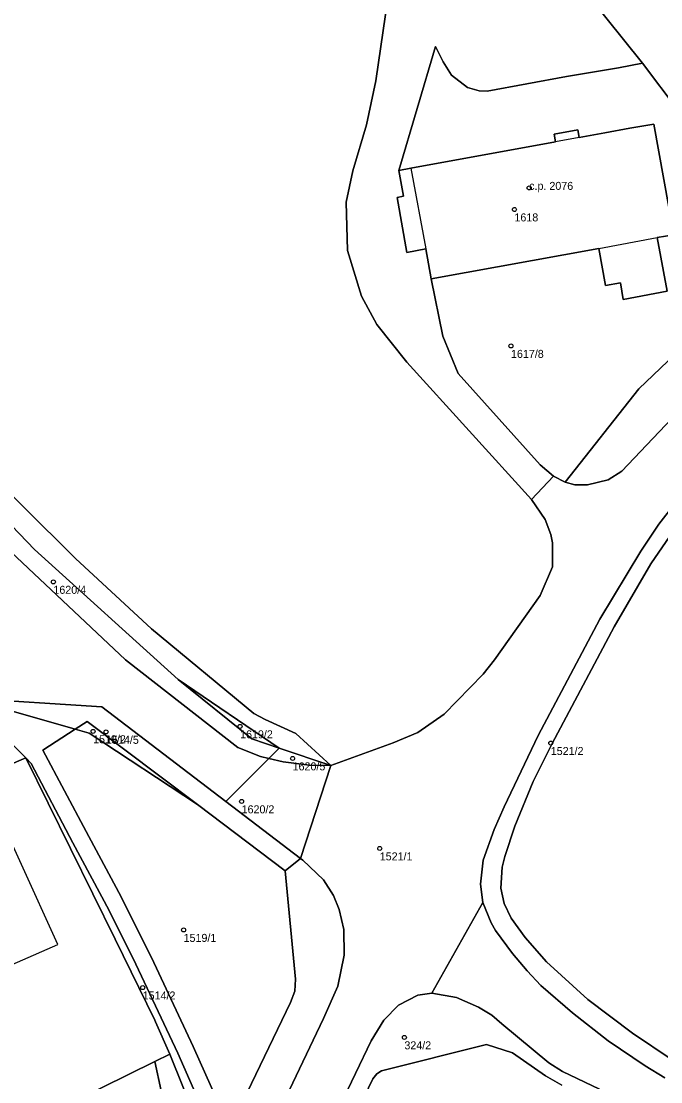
# Model space of a CAD drawing. Extents: x -878211 to -870363, y -1058464 to -1052522.
# Drawn here: x -874750.5 to -874670.5, y -1056026.5 to -1055893.9 of the extents above; entities that cross this region are included whole.
import ezdxf

# ---------------------------------------------------------------- set-up
doc = ezdxf.new("R2010")
doc.units = 0
for name, color, linetype in [('Definiční body', 7, 'Continuous'), ('Polygon budovy', 7, 'Continuous'), ('Polygon parcely', 7, 'Continuous')]:
    doc.layers.add(name, color=color, linetype=linetype)

msp = doc.modelspace()

# ---------------------------------------------------------------- linework, layer by layer
at = {"layer": 'Definiční body'}
for centre in [(-874686.99, -1055914.72994), (-874688.83, -1055917.42994), (-874689.26, -1055934.48994), (-874746.44, -1055963.97994), (-874741.48, -1055982.65994), (-874739.86, -1055982.72994), (-874723.11, -1055982.03994), (-874684.29, -1055984.12994), (-874716.55, -1055986.04994), (-874722.92, -1055991.41994), (-874705.66, -1055997.29994), (-874730.17, -1056007.48994), (-874735.28, -1056014.68994), (-874702.58, -1056020.91994)]:
    msp.add_circle(centre, 0.25, dxfattribs=at)
at = {"layer": 'Polygon budovy'}
for points in [[(-874701.77, -1055912.28), (-874699.91, -1055922.36), (-874699.24, -1055926.08), (-874678.28, -1055922.29), (-874671.01, -1055920.95), (-874668.92, -1055920.58), (-874671.43, -1055906.75), (-874674.4, -1055907.27), (-874677.53, -1055907.83), (-874680.73, -1055908.42), (-874683.69, -1055908.98)], [(-874764.98, -1055993.72), (-874755.99, -1056013.73), (-874745.88, -1056009.32), (-874755, -1055989.3)]]:
    msp.add_lwpolyline(points, close=True, dxfattribs=at)
at = {"layer": 'Polygon parcely'}
for points in [[(-874756.95, -1055947.89), (-874743.69, -1055961.07), (-874734.19, -1055969.86), (-874721.38, -1055980.44), (-874719.97, -1055981.18), (-874716.14, -1055982.94), (-874711.78, -1055986.92), (-874703.97, -1055984.1), (-874700.92, -1055982.82), (-874697.6, -1055980.52), (-874692.73, -1055975.53), (-874691.31, -1055973.73), (-874685.62, -1055965.69), (-874684.06, -1055962.1), (-874684.06, -1055959.08), (-874684.28, -1055958.07), (-874684.99, -1055956.18), (-874686.68, -1055953.68), (-874702.29, -1055936.53), (-874706.04, -1055931.81), (-874707.93, -1055928.26), (-874709.71, -1055922.56), (-874709.86, -1055916.51), (-874709.03, -1055912.59), (-874707.3, -1055906.85), (-874706.13, -1055901.34), (-874704.05, -1055887.02)], [(-874704.05, -1055887.02), (-874706.13, -1055901.34), (-874707.3, -1055906.85), (-874709.03, -1055912.59), (-874709.86, -1055916.51), (-874709.71, -1055922.56), (-874707.93, -1055928.26), (-874706.04, -1055931.81), (-874702.29, -1055936.53), (-874686.68, -1055953.68), (-874683.95, -1055950.78), (-874685.63, -1055949.35), (-874695.87, -1055937.91), (-874697.78, -1055933.25), (-874699.24, -1055926.08), (-874699.91, -1055922.36), (-874702.26, -1055922.81), (-874703.5, -1055915.91), (-874702.69, -1055915.75), (-874703.28, -1055912.55), (-874698.71, -1055897.06), (-874697.73, -1055898.97), (-874696.71, -1055900.66), (-874694.7, -1055902.18), (-874693.25, -1055902.59), (-874692.22, -1055902.64), (-874682.33, -1055900.81), (-874675.84, -1055899.73), (-874672.82, -1055899.15), (-874679.61, -1055890.66)], [(-874679.61, -1055890.66), (-874672.82, -1055899.15), (-874668.36, -1055905.05), (-874663.17, -1055930.38), (-874659.49, -1055927.14), (-874653.58, -1055922.94), (-874645.33, -1055917.81), (-874639.84, -1055915.02), (-874631.91, -1055911.94), (-874623.73, -1055909.15), (-874623.3, -1055907.36), (-874623.18, -1055905.33), (-874623.7, -1055903.03), (-874633.81, -1055890.41)], [(-874668.36, -1055905.05), (-874672.82, -1055899.15), (-874675.84, -1055899.73), (-874682.33, -1055900.81), (-874692.22, -1055902.64), (-874693.25, -1055902.59), (-874694.7, -1055902.18), (-874696.71, -1055900.66), (-874697.73, -1055898.97), (-874698.71, -1055897.06), (-874703.28, -1055912.55), (-874701.77, -1055912.28), (-874683.69, -1055908.98), (-874683.88, -1055908), (-874680.9, -1055907.46), (-874680.73, -1055908.42), (-874677.53, -1055907.83), (-874674.4, -1055907.27), (-874671.43, -1055906.75), (-874668.92, -1055920.58), (-874671.01, -1055920.95), (-874669.74, -1055927.65), (-874675.24, -1055928.66), (-874675.56, -1055926.59), (-874677.45, -1055926.91), (-874678.28, -1055922.29), (-874699.24, -1055926.08), (-874697.78, -1055933.25), (-874695.87, -1055937.91), (-874685.63, -1055949.35), (-874683.95, -1055950.78), (-874682.5, -1055951.51), (-874673.28, -1055939.83), (-874666.08, -1055932.96)], [(-874666.08, -1055932.96), (-874673.28, -1055939.83), (-874682.5, -1055951.51), (-874681.3, -1055951.84), (-874679.71, -1055951.83), (-874677.1, -1055951.24), (-874675.43, -1055950.15), (-874662.18, -1055936.17)], [(-874662.18, -1055936.17), (-874675.43, -1055950.15), (-874677.1, -1055951.24), (-874679.71, -1055951.83), (-874681.3, -1055951.84), (-874682.5, -1055951.51), (-874683.95, -1055950.78), (-874686.68, -1055953.68), (-874684.99, -1055956.18), (-874684.28, -1055958.07), (-874684.06, -1055959.08), (-874684.06, -1055962.1), (-874685.62, -1055965.69), (-874691.31, -1055973.73), (-874692.73, -1055975.53), (-874697.6, -1055980.52), (-874700.92, -1055982.82), (-874703.97, -1055984.1), (-874711.78, -1055986.92), (-874715.56, -1055998.56), (-874715.27, -1055998.76), (-874712.68, -1056001.22), (-874711.42, -1056003.18), (-874710.71, -1056004.93), (-874710.15, -1056007.45), (-874710.12, -1056010.62), (-874710.89, -1056014.52), (-874712.68, -1056018.57), (-874723.79, -1056041.89)], [(-874760.24, -1055948), (-874748.81, -1055959.95), (-874730.86, -1055976.16), (-874718.22, -1055984.76), (-874711.78, -1055986.92), (-874716.14, -1055982.94), (-874719.97, -1055981.18), (-874721.38, -1055980.44), (-874734.19, -1055969.86), (-874743.69, -1055961.07), (-874756.95, -1055947.89)], [(-874718.48, -1056045.86), (-874706.75, -1056021.33), (-874705.13, -1056018.77), (-874703.32, -1056016.88), (-874700.92, -1056015.63), (-874699.15, -1056015.39), (-874692.76, -1056004.06), (-874693.08, -1056001.75), (-874692.72, -1055998.76), (-874691.38, -1055994.94), (-874690.11, -1055992.09), (-874685.85, -1055983.17), (-874678.15, -1055968.65), (-874673.05, -1055960.14), (-874670.77, -1055956.77), (-874668.86, -1055954.3)], [(-874668.86, -1055954.3), (-874670.77, -1055956.77), (-874673.05, -1055960.14), (-874678.15, -1055968.65), (-874685.85, -1055983.17), (-874690.11, -1055992.09), (-874691.38, -1055994.94), (-874692.72, -1055998.76), (-874693.08, -1056001.75), (-874692.76, -1056004.06), (-874691.75, -1056006.58), (-874691.19, -1056007.55), (-874689.08, -1056010.44), (-874687.25, -1056012.6), (-874685.53, -1056014.41), (-874681.58, -1056017.86), (-874677.13, -1056021.34), (-874672.5, -1056024.45), (-874670.04, -1056025.99)], [(-874757.31, -1055978.52), (-874740.38, -1055979.61), (-874724.88, -1055991.44), (-874719.51, -1055986.05), (-874720.55, -1055985.8), (-874723.38, -1055984.67), (-874737.42, -1055973.71), (-874753.92, -1055958.22)], [(-874668.96, -1055957.59), (-874671.77, -1055961.73), (-874676.38, -1055969.58), (-874684.1, -1055984.19), (-874686.47, -1055988.93), (-874688.76, -1055994.5), (-874690.04, -1055998.29), (-874690.37, -1055999.65), (-874690.54, -1056002.26), (-874690.1, -1056004.19), (-874689.22, -1056006), (-874687.47, -1056008.44), (-874684.83, -1056011.49), (-874679.64, -1056016.16), (-874674.07, -1056020.38), (-874669.11, -1056023.72)], [(-874669.11, -1056023.72), (-874674.07, -1056020.38), (-874679.64, -1056016.16), (-874684.83, -1056011.49), (-874687.47, -1056008.44), (-874689.22, -1056006), (-874690.1, -1056004.19), (-874690.54, -1056002.26), (-874690.37, -1055999.65), (-874690.04, -1055998.29), (-874688.76, -1055994.5), (-874686.47, -1055988.93), (-874684.1, -1055984.19), (-874676.38, -1055969.58), (-874671.77, -1055961.73), (-874668.96, -1055957.59)], [(-874723.79, -1056041.89), (-874712.68, -1056018.57), (-874710.89, -1056014.52), (-874710.12, -1056010.62), (-874710.15, -1056007.45), (-874710.71, -1056004.93), (-874711.42, -1056003.18), (-874712.68, -1056001.22), (-874715.27, -1055998.76), (-874715.56, -1055998.56), (-874717.46, -1056000.09), (-874716.19, -1056013.63), (-874716.29, -1056015.13), (-874716.81, -1056016.56), (-874724.38, -1056032.3), (-874728.99, -1056022.04), (-874734.19, -1056010.92), (-874738.25, -1056002.8), (-874742.35, -1055995.2), (-874747.78, -1055985.01), (-874743.71, -1055982.38), (-874757.31, -1055978.52), (-874749.9, -1055985.99), (-874749.22, -1055986.7), (-874744.03, -1055996.59), (-874739.47, -1056005.07), (-874736.12, -1056011.78), (-874730.91, -1056022.87), (-874724.71, -1056036.91)], [(-874670.04, -1056025.99), (-874672.5, -1056024.45), (-874677.13, -1056021.34), (-874681.58, -1056017.86), (-874685.53, -1056014.41), (-874687.25, -1056012.6), (-874689.08, -1056010.44), (-874691.19, -1056007.55), (-874691.75, -1056006.58), (-874692.76, -1056004.06), (-874699.15, -1056015.39), (-874696.05, -1056015.93), (-874693.31, -1056017.12), (-874691.64, -1056018.14), (-874690.41, -1056019.24), (-874684.55, -1056024.09), (-874682.82, -1056025.19), (-874678.22, -1056027.38), (-874668.85, -1056031.63)], [(-874678.22, -1056027.38), (-874682.82, -1056025.19), (-874684.55, -1056024.09), (-874690.41, -1056019.24), (-874691.64, -1056018.14), (-874693.31, -1056017.12), (-874696.05, -1056015.93), (-874699.15, -1056015.39), (-874700.92, -1056015.63), (-874703.32, -1056016.88), (-874705.13, -1056018.77), (-874706.75, -1056021.33), (-874718.48, -1056045.86)], [(-874718.01, -1056050), (-874706.53, -1056026.09), (-874706.04, -1056025.49), (-874705.45, -1056025.1), (-874692.33, -1056021.8), (-874689.09, -1056022.83), (-874684.96, -1056025.73), (-874682.89, -1056026.9)], [(-874682.89, -1056026.9), (-874684.96, -1056025.73), (-874689.09, -1056022.83), (-874692.33, -1056021.8), (-874705.45, -1056025.1), (-874706.04, -1056025.49), (-874706.53, -1056026.09), (-874718.01, -1056050)]]:
    msp.add_lwpolyline(points, dxfattribs=at)
for points in [[(-874703.28, -1055912.55), (-874702.69, -1055915.75), (-874703.5, -1055915.91), (-874702.26, -1055922.81), (-874699.91, -1055922.36), (-874699.24, -1055926.08), (-874678.28, -1055922.29), (-874677.45, -1055926.91), (-874675.56, -1055926.59), (-874675.24, -1055928.66), (-874669.74, -1055927.65), (-874671.01, -1055920.95), (-874668.92, -1055920.58), (-874671.43, -1055906.75), (-874674.4, -1055907.27), (-874677.53, -1055907.83), (-874680.73, -1055908.42), (-874680.9, -1055907.46), (-874683.88, -1055908), (-874683.69, -1055908.98), (-874701.77, -1055912.28)], [(-874768.56, -1055938.23), (-874753.92, -1055958.22), (-874737.42, -1055973.71), (-874723.38, -1055984.67), (-874720.55, -1055985.8), (-874719.51, -1055986.05), (-874718.22, -1055984.76), (-874721.64, -1055983.61), (-874730.86, -1055976.16), (-874748.81, -1055959.95), (-874760.24, -1055948)], [(-874787.87, -1055982.66), (-874772.22, -1055996.04), (-874765.48, -1055992.98), (-874755.06, -1055988.17), (-874749.9, -1055985.99), (-874757.31, -1055978.52), (-874764.37, -1055984.28), (-874766.82, -1055986.47), (-874770.87, -1055989.91), (-874774.61, -1055986.86), (-874784.46, -1055977.65), (-874786.38, -1055974.79), (-874788.76, -1055977.69), (-874790.59, -1055979.93)], [(-874721.64, -1055983.61), (-874718.22, -1055984.76), (-874730.86, -1055976.16)], [(-874742.21, -1055981.41), (-874728.42, -1055991.82), (-874717.46, -1056000.09), (-874715.56, -1055998.56), (-874724.88, -1055991.44), (-874740.38, -1055979.61), (-874757.31, -1055978.52), (-874743.71, -1055982.38)], [(-874741.98, -1055982.87), (-874743.71, -1055982.38), (-874747.78, -1055985.01), (-874742.35, -1055995.2), (-874738.25, -1056002.8), (-874734.19, -1056010.92), (-874728.99, -1056022.04), (-874724.38, -1056032.3), (-874716.81, -1056016.56), (-874716.29, -1056015.13), (-874716.19, -1056013.63), (-874717.46, -1056000.09), (-874728.42, -1055991.82)], [(-874728.42, -1055991.82), (-874742.21, -1055981.41), (-874743.71, -1055982.38), (-874741.98, -1055982.87)], [(-874711.78, -1055986.92), (-874718.22, -1055984.76), (-874719.51, -1055986.05), (-874717.74, -1055986.47), (-874714.44, -1055986.89)], [(-874750.31, -1056032.09), (-874733.76, -1056023.92), (-874731.9, -1056023), (-874733.67, -1056018.96), (-874733.75, -1056018.77), (-874738.71, -1056008.63), (-874749.9, -1055985.99), (-874755.06, -1055988.17), (-874765.48, -1055992.98), (-874764.98, -1055993.72), (-874755.99, -1056013.73), (-874755.89, -1056017.1)], [(-874725.31, -1056039.38), (-874724.68, -1056037.94), (-874724.62, -1056037.43), (-874724.71, -1056036.91), (-874730.91, -1056022.87), (-874736.12, -1056011.78), (-874739.47, -1056005.07), (-874744.03, -1055996.59), (-874749.22, -1055986.7), (-874749.9, -1055985.99), (-874738.71, -1056008.63), (-874733.75, -1056018.77), (-874733.67, -1056018.96), (-874731.9, -1056023)], [(-874711.78, -1055986.92), (-874714.44, -1055986.89), (-874717.74, -1055986.47), (-874719.51, -1055986.05), (-874724.88, -1055991.44), (-874715.56, -1055998.56)], [(-874731.9, -1056023), (-874733.76, -1056023.92), (-874730.6, -1056038.58), (-874731.35, -1056047.24), (-874730.39, -1056047.17), (-874729.48, -1056047.8), (-874725.31, -1056039.38)], [(-874733.76, -1056023.92), (-874750.31, -1056032.09), (-874737.44, -1056062.48), (-874731.81, -1056052.49), (-874731.35, -1056047.24), (-874730.6, -1056038.58)]]:
    msp.add_lwpolyline(points, close=True, dxfattribs=at)

# ---------------------------------------------------------------- texts
at = {"layer": 'Definiční body'}
for s, p in [('c.p. 2076', (-874686.99, -1055914.98)), ('1618', (-874688.83, -1055918.919)), ('1617/8', (-874689.26, -1055935.979)), ('1620/4', (-874746.44, -1055965.469)), ('1619/2', (-874723.11, -1055983.529)), ('1519/2', (-874741.48, -1055984.149)), ('1514/5', (-874739.86, -1055984.219)), ('1521/2', (-874684.29, -1055985.619)), ('1620/5', (-874716.55, -1055987.539)), ('1620/2', (-874722.92, -1055992.909)), ('1521/1', (-874705.66, -1055998.789)), ('1519/1', (-874730.17, -1056008.979)), ('1514/2', (-874735.28, -1056016.179)), ('324/2', (-874702.58, -1056022.409))]:
    msp.add_text(s, height=0.999996, dxfattribs=at).set_placement(p)

doc.saveas('drawing.dxf')
